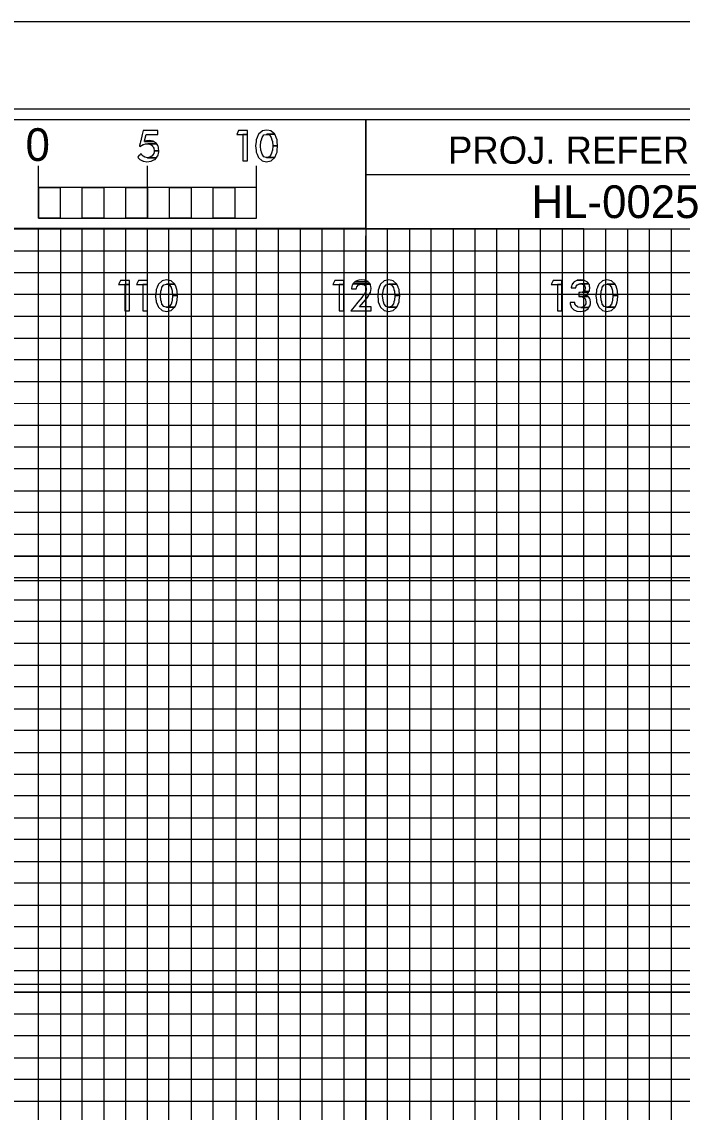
# Model space of a CAD drawing. Extents: x -13 to 323, y -5 to 1431.
# Drawn here: x 264.2 to 294.5, y 824.5 to 874.5 of the extents above; entities that cross this region are included whole.
import ezdxf

# ---------------------------------------------------------------- set-up
doc = ezdxf.new("R2010")
doc.units = 0
for name, color, linetype in [('Prop XS Bar Scale Labels', 7, 'Continuous'), ('Prop XS Offset Labels', 7, 'Continuous'), ('Prop XS Project Number', 7, 'Continuous'), ('Scratch_Level_3', 7, 'Continuous'), ('Sheet Cross Section CELL', 7, 'Continuous'), ('Sheet Cross Section Grid Major CELL', 7, 'Continuous'), ('Sheet Cross Section Grid Middle CELL', 7, 'Continuous'), ('Sheet Cross Section Grid Minor 1 CELL', 7, 'Continuous'), ('Sheet Cross Section Grid Minor 2 CELL', 7, 'Continuous'), ('Sheet Cross Section Scale CELL', 7, 'Continuous'), ('Sheet Cutting Line CELL', 7, 'Continuous'), ('Sheet DOT Grid CELL', 7, 'Continuous'), ('Sheet Plot Border Inside CELL', 7, 'Continuous'), ('Sheet Plot Border Outside CELL', 7, 'Continuous')]:
    doc.layers.add(name, color=color, linetype=linetype)

msp = doc.modelspace()

# ---------------------------------------------------------------- linework, layer by layer
at = {"layer": 'Prop XS Bar Scale Labels'}
for points in [[(269.63, 868.81), (269.627, 868.798), (269.698, 868.798), (269.711, 868.81), (269.727, 868.824), (269.798, 868.867), (269.83, 868.877), (269.9, 868.899), (270.014, 868.905), (270.422, 868.905), (270.414, 868.92), (270.28, 869.015), (269.858, 869.015), (269.861, 869.028), (269.861, 869.028), (269.866, 869.048), (269.941, 869.326), (270.466, 869.326), (270.466, 869.511), (269.803, 869.511), (269.757, 869.326), (269.689, 869.048), (269.684, 869.028), (269.681, 869.015), (269.658, 868.92), (269.654, 868.905), (269.652, 868.899), (269.647, 868.877), (269.644, 868.867), (269.634, 868.824)], [(274.174, 869.511), (274.085, 869.329), (274.583, 869.329), (274.583, 869.511)], [(275.258, 868.125), (275.457, 868.084), (275.652, 868.125), (275.663, 868.127), (275.828, 868.279), (275.454, 868.279), (275.445, 868.281), (275.44, 868.283), (275.335, 868.312), (275.248, 868.425), (275.248, 868.426), (275.248, 868.426), (275.22, 868.527), (275.22, 868.529), (275.2, 868.602), (275.198, 868.606), (275.181, 868.809), (275.181, 868.811), (275.181, 868.813), (275.198, 869.015), (275.219, 869.092), (275.22, 869.094), (275.246, 869.192), (275.247, 869.195), (275.335, 869.31), (275.448, 869.339), (275.452, 869.34), (275.462, 869.343), (275.832, 869.343), (275.669, 869.492), (275.66, 869.494), (275.46, 869.538), (275.46, 869.538), (275.252, 869.494), (275.25, 869.492), (275.088, 869.343), (275.085, 869.34), (275.084, 869.339), (275.072, 869.31), (275.025, 869.195), (275.024, 869.192), (274.983, 869.094), (274.983, 869.092), (274.975, 869.015), (274.954, 868.813), (274.953, 868.811), (274.954, 868.809), (274.974, 868.606), (274.974, 868.602), (274.982, 868.529), (274.982, 868.527), (275.023, 868.426), (275.024, 868.425), (275.07, 868.312), (275.082, 868.283), (275.082, 868.281), (275.085, 868.279), (275.255, 868.127)], [(269.895, 869.028), (269.858, 869.015), (270.28, 869.015), (270.262, 869.028), (270.164, 869.048), (269.953, 869.048)], [(270.091, 869.062), (269.953, 869.048), (270.164, 869.048), (270.091, 869.062)], [(274.374, 869.329), (274.374, 868.12), (274.583, 868.12), (274.583, 869.329)], [(275.719, 869.015), (275.735, 868.813), (275.962, 868.813), (275.942, 869.015), (275.935, 869.092), (275.934, 869.094), (275.934, 869.094), (275.895, 869.192), (275.895, 869.192), (275.893, 869.195), (275.848, 869.31), (275.847, 869.31), (275.835, 869.339), (275.835, 869.34), (275.832, 869.343), (275.462, 869.343), (275.472, 869.34), (275.475, 869.339), (275.582, 869.31), (275.669, 869.195), (275.672, 869.192), (275.698, 869.094), (275.698, 869.092)], [(269.627, 868.798), (269.685, 868.786), (269.698, 868.798)], [(270.103, 868.288), (269.996, 868.269), (270.408, 868.269), (270.423, 868.288), (270.424, 868.289), (270.425, 868.29), (270.425, 868.29), (270.462, 868.336), (270.471, 868.347), (270.473, 868.353), (270.487, 868.405), (270.502, 868.46), (270.525, 868.544), (270.521, 868.591), (270.308, 868.591), (270.3, 868.544), (270.286, 868.46), (270.25, 868.405), (270.217, 868.353), (270.207, 868.347), (270.19, 868.336), (270.116, 868.29), (270.108, 868.289)], [(270.286, 868.711), (270.308, 868.591), (270.521, 868.591), (270.51, 868.711), (270.51, 868.711), (270.507, 868.751), (270.487, 868.786), (270.481, 868.798), (270.475, 868.81), (270.467, 868.824), (270.443, 868.867), (270.438, 868.877), (270.426, 868.899), (270.422, 868.905), (270.014, 868.905), (270.041, 868.899), (270.132, 868.877), (270.146, 868.867), (270.206, 868.824), (270.227, 868.81), (270.234, 868.798), (270.241, 868.786), (270.262, 868.751)], [(275.465, 868.281), (275.454, 868.279), (275.828, 868.279), (275.831, 868.281), (275.833, 868.283), (275.845, 868.312), (275.892, 868.425), (275.892, 868.426), (275.934, 868.527), (275.935, 868.529), (275.942, 868.602), (275.942, 868.606), (275.962, 868.809), (275.963, 868.811), (275.962, 868.813), (275.735, 868.813), (275.735, 868.811), (275.735, 868.809), (275.719, 868.606), (275.718, 868.602), (275.699, 868.529), (275.698, 868.527), (275.671, 868.426), (275.67, 868.425), (275.582, 868.312), (275.47, 868.283)], [(269.829, 868.103), (269.965, 868.084), (270.163, 868.103), (270.171, 868.107), (270.294, 868.167), (270.294, 868.167), (270.344, 868.191), (270.388, 868.245), (270.408, 868.269), (269.996, 868.269), (269.887, 868.288), (269.885, 868.289), (269.882, 868.29), (269.799, 868.336), (269.789, 868.347), (269.783, 868.353), (269.783, 868.353), (269.733, 868.405), (269.7, 868.455), (269.7, 868.455), (269.655, 868.405), (269.608, 868.353), (269.602, 868.347), (269.593, 868.336), (269.551, 868.29), (269.55, 868.289), (269.551, 868.288), (269.566, 868.269), (269.585, 868.245), (269.649, 868.191), (269.677, 868.167), (269.801, 868.107)]]:
    msp.add_lwpolyline(points, close=True, dxfattribs=at)
at = {"layer": 'Prop XS Offset Labels'}
for points in [[(268.76, 862.641), (268.671, 862.459), (269.17, 862.459), (269.17, 862.641)], [(269.587, 862.641), (269.498, 862.459), (269.997, 862.459), (269.997, 862.641)], [(270.672, 861.255), (270.871, 861.214), (271.066, 861.255), (271.077, 861.257), (271.242, 861.409), (270.868, 861.409), (270.858, 861.411), (270.853, 861.413), (270.749, 861.442), (270.662, 861.555), (270.661, 861.556), (270.661, 861.556), (270.634, 861.657), (270.633, 861.659), (270.613, 861.732), (270.612, 861.736), (270.594, 861.939), (270.594, 861.941), (270.595, 861.943), (270.612, 862.145), (270.633, 862.222), (270.633, 862.224), (270.66, 862.322), (270.661, 862.325), (270.749, 862.44), (270.862, 862.469), (270.865, 862.47), (270.876, 862.473), (271.246, 862.473), (271.082, 862.622), (271.074, 862.624), (270.873, 862.668), (270.873, 862.668), (270.665, 862.624), (270.663, 862.622), (270.502, 862.473), (270.499, 862.47), (270.498, 862.469), (270.486, 862.44), (270.439, 862.325), (270.437, 862.322), (270.397, 862.224), (270.397, 862.222), (270.389, 862.145), (270.367, 861.943), (270.367, 861.941), (270.367, 861.939), (270.387, 861.736), (270.388, 861.732), (270.395, 861.659), (270.396, 861.657), (270.437, 861.556), (270.437, 861.555), (270.483, 861.442), (270.495, 861.413), (270.496, 861.411), (270.499, 861.409), (270.669, 861.257)], [(278.581, 862.641), (278.492, 862.459), (278.99, 862.459), (278.99, 862.641)], [(279.507, 862.583), (279.41, 862.479), (280.197, 862.479), (280.108, 862.583)], [(279.512, 862.585), (279.507, 862.583), (280.108, 862.583), (280.106, 862.585), (279.974, 862.645), (279.958, 862.652), (279.794, 862.668), (279.794, 862.668), (279.685, 862.652), (279.637, 862.645)], [(280.851, 861.255), (281.051, 861.214), (281.245, 861.255), (281.256, 861.257), (281.422, 861.409), (281.048, 861.409), (281.038, 861.411), (281.033, 861.413), (280.928, 861.442), (280.841, 861.555), (280.841, 861.556), (280.841, 861.556), (280.813, 861.657), (280.813, 861.659), (280.793, 861.732), (280.792, 861.736), (280.774, 861.939), (280.774, 861.941), (280.774, 861.943), (280.792, 862.145), (280.812, 862.222), (280.813, 862.224), (280.839, 862.322), (280.84, 862.325), (280.928, 862.44), (281.041, 862.469), (281.045, 862.47), (281.055, 862.473), (281.425, 862.473), (281.262, 862.622), (281.254, 862.624), (281.053, 862.668), (281.053, 862.668), (280.845, 862.624), (280.843, 862.622), (280.681, 862.473), (280.678, 862.47), (280.678, 862.469), (280.665, 862.44), (280.618, 862.325), (280.617, 862.322), (280.577, 862.224), (280.576, 862.222), (280.568, 862.145), (280.547, 861.943), (280.547, 861.941), (280.547, 861.939), (280.567, 861.736), (280.567, 861.732), (280.575, 861.659), (280.575, 861.657), (280.616, 861.556), (280.617, 861.555), (280.663, 861.442), (280.675, 861.413), (280.676, 861.411), (280.679, 861.409), (280.848, 861.257)], [(288.581, 862.641), (288.492, 862.459), (288.99, 862.459), (288.99, 862.641)], [(289.42, 862.315), (289.418, 862.297), (289.626, 862.297), (289.627, 862.315), (289.639, 862.365), (289.64, 862.372), (289.641, 862.373), (289.683, 862.433), (289.688, 862.436), (289.696, 862.44), (289.748, 862.47), (289.785, 862.476), (289.795, 862.478), (289.835, 862.485), (290.217, 862.485), (290.165, 862.561), (290.129, 862.582), (290.128, 862.582), (290.022, 862.644), (289.982, 862.65), (289.69, 862.65), (289.678, 862.644), (289.553, 862.582), (289.536, 862.561), (289.471, 862.485), (289.466, 862.478), (289.465, 862.476), (289.463, 862.47), (289.452, 862.44), (289.45, 862.436), (289.449, 862.433), (289.428, 862.373), (289.427, 862.372), (289.425, 862.365)], [(289.853, 862.668), (289.69, 862.65), (289.982, 862.65)], [(290.851, 861.255), (291.051, 861.214), (291.245, 861.255), (291.256, 861.257), (291.422, 861.409), (291.048, 861.409), (291.038, 861.411), (291.033, 861.413), (290.928, 861.442), (290.841, 861.555), (290.841, 861.556), (290.841, 861.556), (290.813, 861.657), (290.813, 861.659), (290.793, 861.732), (290.792, 861.736), (290.774, 861.939), (290.774, 861.941), (290.774, 861.943), (290.792, 862.145), (290.812, 862.222), (290.813, 862.224), (290.839, 862.322), (290.84, 862.325), (290.928, 862.44), (291.041, 862.469), (291.045, 862.47), (291.055, 862.473), (291.425, 862.473), (291.262, 862.622), (291.254, 862.624), (291.053, 862.668), (291.053, 862.668), (290.845, 862.624), (290.843, 862.622), (290.681, 862.473), (290.678, 862.47), (290.678, 862.469), (290.665, 862.44), (290.618, 862.325), (290.617, 862.322), (290.577, 862.224), (290.576, 862.222), (290.568, 862.145), (290.547, 861.943), (290.547, 861.941), (290.547, 861.939), (290.567, 861.736), (290.567, 861.732), (290.575, 861.659), (290.575, 861.657), (290.616, 861.556), (290.617, 861.555), (290.663, 861.442), (290.675, 861.413), (290.676, 861.411), (290.679, 861.409), (290.848, 861.257)], [(268.961, 862.459), (268.961, 861.25), (269.17, 861.25), (269.17, 862.459)], [(269.788, 862.459), (269.788, 861.25), (269.997, 861.25), (269.997, 862.459)], [(271.132, 862.145), (271.149, 861.943), (271.376, 861.943), (271.356, 862.145), (271.349, 862.222), (271.348, 862.224), (271.348, 862.224), (271.308, 862.322), (271.308, 862.322), (271.307, 862.325), (271.261, 862.44), (271.261, 862.44), (271.249, 862.469), (271.249, 862.47), (271.246, 862.473), (270.876, 862.473), (270.885, 862.47), (270.889, 862.469), (270.995, 862.44), (271.083, 862.325), (271.085, 862.322), (271.111, 862.224), (271.112, 862.222)], [(278.781, 862.459), (278.781, 861.25), (278.99, 861.25), (278.99, 862.459)], [(279.465, 861.432), (279.313, 861.25), (280.253, 861.25), (280.253, 861.432), (279.719, 861.432), (279.898, 861.638), (280.095, 861.879), (280.097, 861.881), (280.208, 862.069), (280.208, 862.069), (280.211, 862.074), (280.235, 862.193), (280.247, 862.254), (280.252, 862.279), (280.25, 862.29), (280.249, 862.293), (280.236, 862.354), (280.235, 862.36), (280.233, 862.37), (280.222, 862.421), (280.222, 862.421), (280.219, 862.435), (280.213, 862.461), (280.211, 862.464), (280.207, 862.468), (279.839, 862.468), (279.85, 862.464), (279.858, 862.461), (279.933, 862.435), (279.946, 862.421), (279.996, 862.37), (280, 862.36), (280.002, 862.354), (280.022, 862.293), (280.022, 862.29), (280.022, 862.279), (280.022, 862.254), (280.021, 862.193), (279.973, 862.074), (279.972, 862.069), (279.839, 861.881), (279.838, 861.879), (279.637, 861.638)], [(279.349, 862.279), (279.347, 862.254), (279.567, 862.254), (279.569, 862.279), (279.57, 862.29), (279.571, 862.293), (279.593, 862.354), (279.598, 862.36), (279.606, 862.37), (279.645, 862.421), (279.673, 862.435), (279.725, 862.461), (279.73, 862.464), (279.839, 862.468), (280.207, 862.468), (280.197, 862.479), (279.41, 862.479), (279.405, 862.468), (279.403, 862.464), (279.402, 862.461), (279.39, 862.435), (279.384, 862.421), (279.361, 862.37), (279.357, 862.36), (279.356, 862.354), (279.35, 862.293), (279.35, 862.29)], [(281.312, 862.145), (281.328, 861.943), (281.555, 861.943), (281.536, 862.145), (281.528, 862.222), (281.528, 862.224), (281.527, 862.224), (281.488, 862.322), (281.488, 862.322), (281.487, 862.325), (281.441, 862.44), (281.44, 862.44), (281.429, 862.469), (281.428, 862.47), (281.425, 862.473), (281.055, 862.473), (281.065, 862.47), (281.068, 862.469), (281.175, 862.44), (281.262, 862.325), (281.265, 862.322), (281.291, 862.224), (281.291, 862.222)], [(288.781, 862.459), (288.781, 861.25), (288.99, 861.25), (288.99, 862.459)], [(289.765, 861.956), (289.765, 861.9), (290.194, 861.9), (290.119, 861.956), (290.029, 861.983), (290.095, 862), (290.181, 862.053), (290.2, 862.084), (290.201, 862.085), (290.207, 862.095), (289.915, 862.095), (289.83, 862.085), (289.765, 862.084), (289.765, 862.053), (289.765, 862), (289.765, 861.983)], [(290.007, 862.155), (289.988, 862.131), (290.23, 862.131), (290.246, 862.155), (290.254, 862.201), (290.271, 862.289), (290.272, 862.295), (290.272, 862.297), (290.269, 862.315), (290.26, 862.365), (290.259, 862.372), (290.259, 862.373), (290.259, 862.373), (290.249, 862.433), (290.248, 862.436), (290.248, 862.44), (290.227, 862.47), (290.223, 862.476), (290.222, 862.478), (290.217, 862.485), (289.835, 862.485), (289.901, 862.478), (289.919, 862.476), (289.931, 862.47), (289.986, 862.44), (289.995, 862.436), (289.997, 862.433), (290.04, 862.373), (290.04, 862.372), (290.042, 862.365), (290.051, 862.315), (290.054, 862.297), (290.055, 862.295), (290.056, 862.289), (290.041, 862.201)], [(289.988, 862.131), (289.915, 862.095), (290.207, 862.095), (290.23, 862.131)], [(291.312, 862.145), (291.328, 861.943), (291.555, 861.943), (291.536, 862.145), (291.528, 862.222), (291.528, 862.224), (291.527, 862.224), (291.488, 862.322), (291.488, 862.322), (291.487, 862.325), (291.441, 862.44), (291.44, 862.44), (291.429, 862.469), (291.428, 862.47), (291.425, 862.473), (291.055, 862.473), (291.065, 862.47), (291.068, 862.469), (291.175, 862.44), (291.262, 862.325), (291.265, 862.322), (291.291, 862.224), (291.291, 862.222)], [(270.878, 861.411), (270.868, 861.409), (271.242, 861.409), (271.245, 861.411), (271.247, 861.413), (271.259, 861.442), (271.305, 861.555), (271.306, 861.556), (271.348, 861.657), (271.348, 861.659), (271.355, 861.732), (271.356, 861.736), (271.376, 861.939), (271.376, 861.941), (271.376, 861.943), (271.149, 861.943), (271.149, 861.941), (271.148, 861.939), (271.132, 861.736), (271.132, 861.732), (271.112, 861.659), (271.112, 861.657), (271.085, 861.556), (271.084, 861.555), (270.995, 861.442), (270.883, 861.413)], [(281.058, 861.411), (281.048, 861.409), (281.422, 861.409), (281.425, 861.411), (281.426, 861.413), (281.438, 861.442), (281.485, 861.555), (281.485, 861.556), (281.527, 861.657), (281.528, 861.659), (281.535, 861.732), (281.535, 861.736), (281.555, 861.939), (281.556, 861.941), (281.555, 861.943), (281.328, 861.943), (281.328, 861.941), (281.328, 861.939), (281.312, 861.736), (281.312, 861.732), (281.292, 861.659), (281.291, 861.657), (281.264, 861.556), (281.263, 861.555), (281.175, 861.442), (281.063, 861.413)], [(289.677, 861.229), (289.854, 861.214), (289.936, 861.229), (290.042, 861.248), (290.123, 861.297), (290.187, 861.336), (290.228, 861.399), (290.229, 861.401), (289.849, 861.401), (289.72, 861.416), (289.711, 861.423), (289.639, 861.471), (289.628, 861.479), (289.626, 861.482), (289.608, 861.516), (289.584, 861.562), (289.584, 861.567), (289.58, 861.62), (289.58, 861.625), (289.361, 861.625), (289.362, 861.62), (289.369, 861.567), (289.37, 861.562), (289.377, 861.516), (289.391, 861.482), (289.392, 861.479), (289.395, 861.471), (289.415, 861.423), (289.418, 861.416), (289.425, 861.401), (289.426, 861.399), (289.49, 861.336), (289.53, 861.297), (289.635, 861.248)], [(289.925, 861.416), (289.849, 861.401), (290.229, 861.401), (290.239, 861.416), (290.243, 861.423), (290.243, 861.423), (290.275, 861.471), (290.277, 861.479), (290.277, 861.482), (290.283, 861.516), (290.292, 861.562), (290.293, 861.567), (290.303, 861.62), (290.297, 861.662), (290.285, 861.751), (290.283, 861.763), (290.25, 861.826), (290.223, 861.877), (290.222, 861.88), (290.197, 861.898), (290.194, 861.9), (289.81, 861.9), (289.877, 861.898), (289.951, 861.88), (289.963, 861.877), (290.033, 861.826), (290.07, 861.763), (290.077, 861.751), (290.092, 861.662), (290.088, 861.62), (290.082, 861.567), (290.08, 861.562), (290.057, 861.516), (290.039, 861.482), (290.035, 861.479), (290.025, 861.471), (289.957, 861.423)], [(291.058, 861.411), (291.048, 861.409), (291.422, 861.409), (291.425, 861.411), (291.426, 861.413), (291.438, 861.442), (291.485, 861.555), (291.485, 861.556), (291.527, 861.657), (291.528, 861.659), (291.535, 861.732), (291.535, 861.736), (291.555, 861.939), (291.556, 861.941), (291.555, 861.943), (291.328, 861.943), (291.328, 861.941), (291.328, 861.939), (291.312, 861.736), (291.312, 861.732), (291.292, 861.659), (291.291, 861.657), (291.264, 861.556), (291.263, 861.555), (291.175, 861.442), (291.063, 861.413)]]:
    msp.add_lwpolyline(points, close=True, dxfattribs=at)
at = {"layer": 'Scratch_Level_3'}
msp.add_lwpolyline([(20, 848.886), (300, 848.886), (300, 830.355), (20, 830.355)], close=True, dxfattribs=at)
at = {"layer": 'Sheet Cross Section CELL'}
for p, q in [((280, 867.5), (280, 865)), ((320, 867.49), (280, 867.49)), ((280, 865), (320, 865))]:
    msp.add_line(p, q, dxfattribs=at)
for points in [[(320, 870), (0, 870), (0, 660), (320, 660)], [(280, 870), (260, 870), (260, 865.03), (280, 865.03)], [(320, 870), (280, 870), (280, 865), (320, 865)]]:
    msp.add_lwpolyline(points, close=True, dxfattribs=at)
at = {"layer": 'Sheet Cross Section Grid Major CELL'}
for p, q in [((270, 660), (270, 865)), ((290, 865), (280, 865)), ((280, 865), (280, 660)), ((290, 660), (290, 865))]:
    msp.add_line(p, q, dxfattribs=at)
for points in [[(0, 860), (320, 860), (320, 850), (0, 850)], [(0, 840), (320, 840), (320, 830), (0, 830)]]:
    msp.add_lwpolyline(points, dxfattribs=at)
at = {"layer": 'Sheet Cross Section Grid Middle CELL'}
for points in [[(255, 660), (255, 870), (259.93, 870), (260, 870), (260, 865), (264.99, 865), (264.99, 660)], [(0, 865), (275, 865)], [(275, 660), (275, 865), (285, 865), (285, 660)], [(0, 845), (320, 845), (320, 855), (0, 855)], [(0, 825), (320, 825), (320, 835), (0, 835)]]:
    msp.add_lwpolyline(points, dxfattribs=at)
at = {"layer": 'Sheet Cross Section Grid Minor 1 CELL'}
msp.add_line((0, 864), (320, 864), dxfattribs=at)
for points in [[(0, 863), (270, 863), (320, 863), (320, 862), (0, 862)], [(0, 861), (320, 861), (320, 859), (0, 859)], [(0, 858), (320, 858), (320, 857), (0, 856.98)], [(0, 856), (320, 856), (320, 854), (0, 854)], [(0, 853), (320, 853), (320, 852), (0, 852)], [(0, 851), (320, 851), (320, 849), (0, 849)], [(0, 848), (320, 848), (320, 847), (0, 847)], [(0, 846), (320, 846), (320, 844), (0, 844)], [(0, 843), (320, 843), (320, 842), (0, 842)], [(0, 841), (320, 841), (320, 839), (0, 839)], [(0, 838), (320, 838), (320, 837), (0, 837)], [(0, 836), (320, 836), (320, 833.95), (320, 833), (320, 832), (0, 832)], [(0, 834), (320, 834), (320, 833), (0, 833)], [(0, 831), (320, 831), (320, 829), (0, 829.03)], [(0, 829.03), (320, 829), (320, 828), (0, 828)], [(0, 827), (320, 827), (320, 826), (0, 826)]]:
    msp.add_lwpolyline(points, dxfattribs=at)
at = {"layer": 'Sheet Cross Section Grid Minor 2 CELL'}
for p, q in [((267, 865), (266.01, 865)), ((266.01, 865), (266.01, 660)), ((267, 660), (267, 865)), ((269, 865), (268, 865)), ((268, 865), (268, 660)), ((269, 660), (269, 865))]:
    msp.add_line(p, q, dxfattribs=at)
for points in [[(270, 660), (270.98, 660), (270.98, 865), (272, 865), (272, 660)], [(272, 660), (273, 660), (273, 865), (274.05, 865), (274.05, 660)], [(275, 660), (276, 660), (276, 865), (277, 865), (277, 660)], [(277, 660), (278, 660), (278, 865), (279, 865), (279, 660)], [(280, 660), (281, 660), (281, 865), (282, 865), (282, 660)], [(282, 660), (283, 660), (283, 865), (284, 865), (284, 660)], [(285, 660), (286, 660), (286, 865), (287, 865), (287, 660)], [(287, 660), (288, 660), (288, 865), (289, 865), (289, 660)], [(290, 660), (291, 660), (291, 865), (292, 865), (292, 660)], [(292, 660), (293, 660), (293, 865), (294, 865), (294, 660)]]:
    msp.add_lwpolyline(points, dxfattribs=at)
at = {"layer": 'Sheet Cross Section Scale CELL'}
for p, q in [((265, 865.49), (265, 867.9)), ((265, 866.9), (265, 867.9)), ((270, 865.49), (270, 867.9)), ((275, 865.49), (275, 867.9)), ((275, 866.9), (275, 867.9))]:
    msp.add_line(p, q, dxfattribs=at)
for points in [[(275, 866.9), (265, 866.9), (265, 865.49), (275, 865.49)], [(265, 866.9), (266, 866.9), (266, 865.49), (265, 865.49)], [(267, 866.9), (268, 866.9), (268, 865.49), (267, 865.49)], [(269, 866.9), (270, 866.9), (270, 865.49), (269, 865.49)], [(271, 866.9), (272, 866.9), (272, 865.49), (271, 865.49)], [(273, 866.9), (274, 866.9), (274, 865.49), (273, 865.49)]]:
    msp.add_lwpolyline(points, close=True, dxfattribs=at)
at = {"layer": 'Sheet Cutting Line CELL'}
msp.add_line((323.3, 874.5), (-13.4, 874.5), dxfattribs=at)
at = {"layer": 'Sheet DOT Grid CELL'}
for p, q in [((270, 660), (270, 864.687)), ((280, 660), (280, 864.687)), ((290, 660), (290, 864.687)), ((0, 860), (320, 860)), ((0, 850), (320, 850)), ((0, 840), (320, 840)), ((0, 830), (320, 830))]:
    msp.add_line(p, q, dxfattribs=at)
at = {"layer": 'Sheet Plot Border Inside CELL'}
msp.add_lwpolyline([(-10.8, 659.5), (322.4, 659.5), (322.4, 870.5), (-10.8, 870.5)], close=True, dxfattribs=at)
at = {"layer": 'Sheet Plot Border Outside CELL'}
msp.add_lwpolyline([(-13.4, 655.5), (323.3, 655.5), (323.3, 874.5), (-13.4, 874.5)], close=True, dxfattribs=at)

# ---------------------------------------------------------------- texts
at = {"layer": 'Prop XS Project Number'}
msp.add_text('HL-0025', height=1.5, dxfattribs=at).set_placement((287.598, 865.5))
at = {"layer": 'Sheet Cross Section CELL'}
msp.add_text('PROJ. REFERENCE NO.', height=1.24998, dxfattribs=at).set_placement((283.77, 867.99))
at = {"layer": 'Sheet Cross Section Scale CELL'}
msp.add_text('0', height=1.5, dxfattribs=at).set_placement((264.41, 868.12))

doc.saveas('drawing.dxf')
